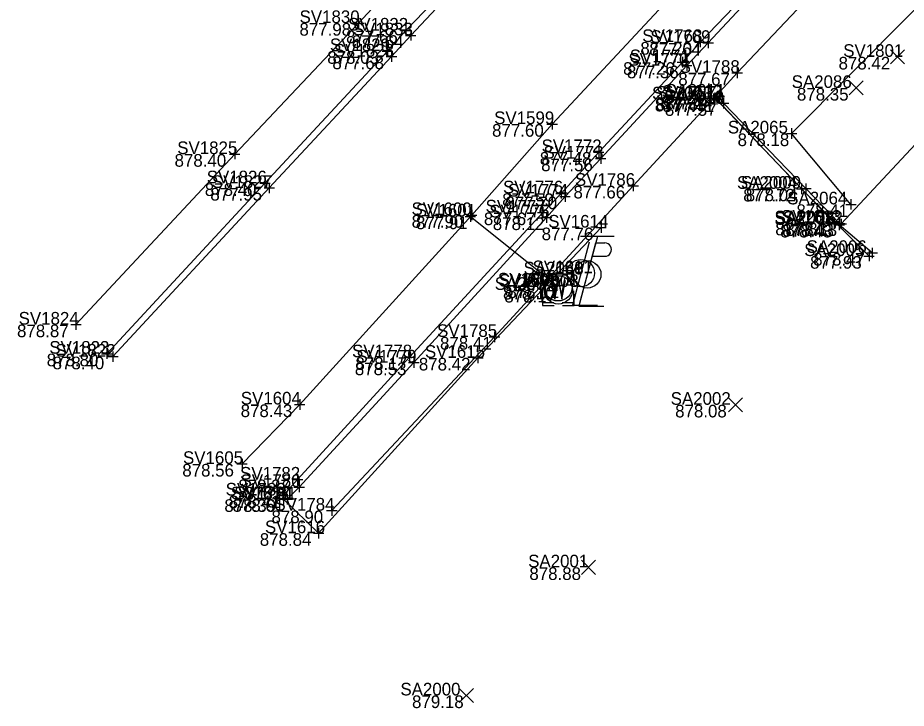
# Model space of a CAD drawing. Extents: x 1480001 to 1480402, y 379235 to 379603.
# Drawn here: x 1480030 to 1480114.4, y 379252.7 to 379318.4 of the extents above; entities that cross this region are included whole.
import ezdxf

# ---------------------------------------------------------------- set-up
doc = ezdxf.new("R2010")
doc.units = 0
for name, color, linetype in [('LT_X_Poles', 7, 'Continuous'), ('PV_X_Curb', 7, 'Continuous'), ('PV_X_Driveway', 7, 'Continuous'), ('PV_X_Parking_Lot', 7, 'Continuous'), ('PV_X_Walk', 7, 'Continuous'), ('SV_X_Break_Lines', 7, 'Continuous'), ('SV_X_Random_Point', 7, 'Continuous'), ('SV_X_Shot_Marker', 7, 'Continuous'), ('SV_X_Text_Elevation', 7, 'Continuous'), ('SV_X_Text_Name', 7, 'Continuous'), ('UT_X_Misc_Cells', 7, 'Continuous'), ('UT_X_Water', 7, 'Continuous'), ('UT_X_Water_Cells', 7, 'Continuous')]:
    doc.layers.add(name, color=color, linetype=linetype)

msp = doc.modelspace()

# ---------------------------------------------------------------- linework, layer by layer
at = {"layer": 'LT_X_Poles'}
for points in [[(1480084.258, 379297.063), (1480082.683, 379291.078), (1480085.046, 379291.078)], [(1480084.866, 379296.951), (1480083.291, 379290.966), (1480085.655, 379290.966)]]:
    msp.add_lwpolyline(points, dxfattribs=at)
for centre in [(1480083.471, 379294.11), (1480084.079, 379293.997)]:
    msp.add_circle(centre, 1.3, dxfattribs=at)
at = {"layer": 'PV_X_Curb'}
for points in [[(1480155.238, 379379.795), (1480153.548, 379379.014), (1480146.824, 379371.927), (1480145.567, 379370.605), (1480143.964, 379368.78), (1480128.12, 379351.892), (1480112.56, 379335.214), (1480098.785, 379320.255), (1480094.793, 379316.092), (1480093.124, 379314.172), (1480085.166, 379305.624), (1480081.585, 379301.702), (1480079.854, 379299.882), (1480067.172, 379286.11), (1480056.531, 379274.485), (1480055.169, 379272.969)], [(1480155.431, 379379.884), (1480153.98, 379378.667), (1480147.216, 379371.505), (1480146.047, 379370.27), (1480144.119, 379368.047), (1480128.647, 379351.629), (1480112.741, 379334.357), (1480099.146, 379319.858), (1480095.569, 379316.008), (1480093.53, 379313.846), (1480085.356, 379305.01), (1480081.967, 379301.397), (1480080.218, 379299.413), (1480067.589, 379285.613), (1480056.688, 379273.774), (1480055.547, 379272.623)], [(1480038.409, 379286.458), (1480053.445, 379302.656), (1480065.083, 379315.224), (1480066.832, 379317.181), (1480073.782, 379324.407), (1480080.94, 379332.144), (1480082.529, 379333.877), (1480097.272, 379349.731), (1480114.906, 379368.678)], [(1480038.979, 379286.174), (1480053.858, 379302.215), (1480065.464, 379314.71), (1480067.296, 379316.727), (1480074.111, 379324.008), (1480081.345, 379331.835), (1480082.794, 379333.357), (1480097.622, 379349.287), (1480115.163, 379368.135)], [(1480111.162, 379296.037), (1480108.032, 379298.711), (1480108.041, 379298.85), (1480104.856, 379302.149), (1480097.04, 379310.274), (1480096.612, 379310.903)]]:
    msp.add_lwpolyline(points, dxfattribs=at)
at = {"layer": 'PV_X_Driveway'}
msp.add_line((1480096.199, 379310.793), (1480107.531, 379298.913), dxfattribs=at)
msp.add_lwpolyline([(1480085.383, 379298.448), (1480073.674, 379286.062), (1480058.546, 379269.388), (1480055.218, 379272.613)], dxfattribs=at)
at = {"layer": 'PV_X_Parking_Lot'}
msp.add_lwpolyline([(1480096.393, 379310.64), (1480104.454, 379302.13), (1480110.858, 379295.74)], dxfattribs=at)
at = {"layer": 'PV_X_Walk'}
for points in [[(1480035.484, 379289.224), (1480050.568, 379305.437), (1480062.335, 379317.896), (1480064.038, 379319.719), (1480070.805, 379327.066), (1480078.054, 379334.946), (1480079.953, 379336.866), (1480094.208, 379352.393), (1480112.048, 379371.575), (1480117.348, 379377.211), (1480119.911, 379379.906), (1480121.511, 379381.77), (1480134.604, 379395.58), (1480136.695, 379398.148), (1480138.778, 379401.149), (1480140.004, 379404.725), (1480140.577, 379408.06), (1480140.982, 379411.311), (1480140.871, 379414.584), (1480140.225, 379417.636), (1480139.184, 379419.586), (1480133.124, 379425.845), (1480132.903, 379425.968), (1480114.834, 379442.96)], [(1480059.793, 379271.54), (1480075.261, 379288.048), (1480088.444, 379302.419), (1480096.088, 379310.695), (1480098.33, 379313.163), (1480111.975, 379327.613), (1480128.977, 379345.933), (1480145.46, 379363.52), (1480153.413, 379372.021), (1480155.772, 379374.786), (1480158.213, 379377.107), (1480160.137, 379378.801), (1480161.631, 379379.994)], [(1480108.223, 379298.793), (1480126.311, 379318.205), (1480145.385, 379338.742), (1480160.312, 379354.639), (1480170.225, 379345.82), (1480179.011, 379355.326), (1480188.24, 379365.647)]]:
    msp.add_lwpolyline(points, dxfattribs=at)
at = {"layer": 'SV_X_Break_Lines'}
msp.add_lwpolyline([(1480109.136, 379300.654), (1480103.503, 379307.396), (1480120.541, 379324.578), (1480124.787, 379337.805), (1480137.007, 379352.173), (1480144.932, 379357.565), (1480149.611, 379361.971), (1480150.052, 379364.189), (1480148.777, 379365.458), (1480163.875, 379379.601), (1480168.818, 379380.654), (1480172.802, 379381.332), (1480178.472, 379378.317), (1480184.655, 379372.421), (1480187.645, 379366.317)], dxfattribs=at)
at = {"layer": 'SV_X_Random_Point'}
for p, q in [((1480112.896, 379314.014), (1480114.23, 379315.349)), ((1480112.896, 379315.349), (1480114.23, 379314.014)), ((1480108.959, 379311.057), (1480110.292, 379312.392)), ((1480108.959, 379312.392), (1480110.292, 379311.057)), ((1480097.488, 379280.931), (1480098.821, 379282.266)), ((1480097.488, 379282.266), (1480098.821, 379280.931)), ((1480083.521, 379265.473), (1480084.854, 379266.808)), ((1480083.521, 379266.808), (1480084.854, 379265.473)), ((1480071.916, 379253.293), (1480073.249, 379254.628)), ((1480071.916, 379254.628), (1480073.249, 379253.293))]:
    msp.add_line(p, q, dxfattribs=at)
at = {"layer": 'SV_X_Shot_Marker'}
for p, q in [((1480061.835, 379317.896), (1480062.835, 379317.896)), ((1480062.335, 379318.396), (1480062.335, 379317.396)), ((1480062.335, 379317.896), (1480062.335, 379317.896)), ((1480066.832, 379317.681), (1480066.832, 379316.681)), ((1480066.332, 379317.181), (1480067.332, 379317.181)), ((1480066.832, 379317.181), (1480066.832, 379317.181)), ((1480067.296, 379317.227), (1480067.296, 379316.227)), ((1480066.796, 379316.727), (1480067.796, 379316.727)), ((1480067.296, 379316.727), (1480067.296, 379316.727)), ((1480094.293, 379316.092), (1480095.293, 379316.092)), ((1480094.793, 379316.592), (1480094.793, 379315.592)), ((1480094.793, 379316.092), (1480094.793, 379316.092)), ((1480095.069, 379316.008), (1480096.069, 379316.008)), ((1480095.569, 379316.508), (1480095.569, 379315.508)), ((1480095.569, 379316.008), (1480095.569, 379316.008)), ((1480064.583, 379315.224), (1480065.583, 379315.224)), ((1480065.083, 379315.724), (1480065.083, 379314.724)), ((1480065.083, 379315.224), (1480065.083, 379315.224)), ((1480065.464, 379315.21), (1480065.464, 379314.21)), ((1480064.964, 379314.71), (1480065.964, 379314.71)), ((1480065.464, 379314.71), (1480065.464, 379314.71)), ((1480093.124, 379314.672), (1480093.124, 379313.672)), ((1480093.53, 379314.346), (1480093.53, 379313.346)), ((1480092.624, 379314.172), (1480093.624, 379314.172)), ((1480093.03, 379313.846), (1480094.03, 379313.846)), ((1480093.124, 379314.172), (1480093.124, 379314.172)), ((1480093.53, 379313.846), (1480093.53, 379313.846)), ((1480098.33, 379313.663), (1480098.33, 379312.663)), ((1480097.83, 379313.163), (1480098.83, 379313.163)), ((1480098.33, 379313.163), (1480098.33, 379313.163)), ((1480096.088, 379311.195), (1480096.088, 379310.195)), ((1480096.112, 379310.903), (1480097.112, 379310.903)), ((1480096.199, 379311.293), (1480096.199, 379310.293)), ((1480096.393, 379311.14), (1480096.393, 379310.14)), ((1480096.612, 379311.403), (1480096.612, 379310.403)), ((1480096.612, 379310.903), (1480096.612, 379310.903)), ((1480095.588, 379310.695), (1480096.588, 379310.695)), ((1480095.699, 379310.793), (1480096.699, 379310.793)), ((1480095.893, 379310.64), (1480096.893, 379310.64)), ((1480096.088, 379310.695), (1480096.088, 379310.695)), ((1480096.199, 379310.793), (1480096.199, 379310.793)), ((1480096.393, 379310.64), (1480096.393, 379310.64)), ((1480096.54, 379310.274), (1480097.54, 379310.274)), ((1480097.04, 379310.774), (1480097.04, 379309.774)), ((1480097.04, 379310.274), (1480097.04, 379310.274)), ((1480080.736, 379308.789), (1480080.736, 379307.789)), ((1480080.236, 379308.289), (1480081.236, 379308.289)), ((1480080.736, 379308.289), (1480080.736, 379308.289)), ((1480103.503, 379307.896), (1480103.503, 379306.896)), ((1480103.003, 379307.396), (1480104.003, 379307.396)), ((1480103.503, 379307.396), (1480103.503, 379307.396)), ((1480050.568, 379305.937), (1480050.568, 379304.937)), ((1480085.166, 379306.124), (1480085.166, 379305.124)), ((1480050.068, 379305.437), (1480051.068, 379305.437)), ((1480050.568, 379305.437), (1480050.568, 379305.437)), ((1480084.666, 379305.624), (1480085.666, 379305.624)), ((1480084.856, 379305.01), (1480085.856, 379305.01)), ((1480085.166, 379305.624), (1480085.166, 379305.624)), ((1480085.356, 379305.51), (1480085.356, 379304.51)), ((1480085.356, 379305.01), (1480085.356, 379305.01)), ((1480052.945, 379302.656), (1480053.945, 379302.656)), ((1480053.445, 379303.156), (1480053.445, 379302.156)), ((1480053.445, 379302.656), (1480053.445, 379302.656)), ((1480053.858, 379302.715), (1480053.858, 379301.715)), ((1480088.444, 379302.919), (1480088.444, 379301.919)), ((1480104.454, 379302.63), (1480104.454, 379301.63)), ((1480104.856, 379302.649), (1480104.856, 379301.649)), ((1480053.358, 379302.215), (1480054.358, 379302.215)), ((1480053.858, 379302.215), (1480053.858, 379302.215)), ((1480081.085, 379301.702), (1480082.085, 379301.702)), ((1480081.585, 379302.202), (1480081.585, 379301.202)), ((1480081.585, 379301.702), (1480081.585, 379301.702)), ((1480081.967, 379301.897), (1480081.967, 379300.897)), ((1480087.944, 379302.419), (1480088.944, 379302.419)), ((1480088.444, 379302.419), (1480088.444, 379302.419)), ((1480103.954, 379302.13), (1480104.954, 379302.13)), ((1480104.356, 379302.149), (1480105.356, 379302.149)), ((1480104.454, 379302.13), (1480104.454, 379302.13)), ((1480104.856, 379302.149), (1480104.856, 379302.149)), ((1480081.467, 379301.397), (1480082.467, 379301.397)), ((1480081.967, 379301.397), (1480081.967, 379301.397)), ((1480109.136, 379301.154), (1480109.136, 379300.154)), ((1480072.97, 379299.999), (1480072.97, 379298.999)), ((1480073.091, 379300.137), (1480073.091, 379299.137)), ((1480079.854, 379300.382), (1480079.854, 379299.382)), ((1480080.218, 379299.913), (1480080.218, 379298.913)), ((1480108.636, 379300.654), (1480109.636, 379300.654)), ((1480109.136, 379300.654), (1480109.136, 379300.654)), ((1480072.47, 379299.499), (1480073.47, 379299.499)), ((1480072.591, 379299.637), (1480073.591, 379299.637)), ((1480072.97, 379299.499), (1480072.97, 379299.499)), ((1480073.091, 379299.637), (1480073.091, 379299.637)), ((1480079.354, 379299.882), (1480080.354, 379299.882)), ((1480079.718, 379299.413), (1480080.718, 379299.413)), ((1480079.854, 379299.882), (1480079.854, 379299.882)), ((1480080.218, 379299.413), (1480080.218, 379299.413)), ((1480107.531, 379299.413), (1480107.531, 379298.413)), ((1480108.032, 379299.211), (1480108.032, 379298.211)), ((1480108.041, 379299.35), (1480108.041, 379298.35)), ((1480108.223, 379299.293), (1480108.223, 379298.293)), ((1480084.883, 379298.448), (1480085.883, 379298.448)), ((1480085.383, 379298.948), (1480085.383, 379297.948)), ((1480085.383, 379298.448), (1480085.383, 379298.448)), ((1480107.031, 379298.913), (1480108.031, 379298.913)), ((1480107.531, 379298.913), (1480107.531, 379298.913)), ((1480107.532, 379298.711), (1480108.532, 379298.711)), ((1480107.541, 379298.85), (1480108.541, 379298.85)), ((1480107.723, 379298.793), (1480108.723, 379298.793)), ((1480108.032, 379298.711), (1480108.032, 379298.711)), ((1480108.041, 379298.85), (1480108.041, 379298.85)), ((1480108.223, 379298.793), (1480108.223, 379298.793)), ((1480111.162, 379296.537), (1480111.162, 379295.537)), ((1480110.358, 379295.74), (1480111.358, 379295.74)), ((1480110.662, 379296.037), (1480111.662, 379296.037)), ((1480110.858, 379296.24), (1480110.858, 379295.24)), ((1480110.858, 379295.74), (1480110.858, 379295.74)), ((1480111.162, 379296.037), (1480111.162, 379296.037)), ((1480081.181, 379293.441), (1480081.181, 379292.441)), ((1480080.681, 379292.941), (1480081.681, 379292.941)), ((1480081.181, 379292.941), (1480081.181, 379292.941)), ((1480034.984, 379289.224), (1480035.984, 379289.224)), ((1480035.484, 379289.724), (1480035.484, 379288.724)), ((1480035.484, 379289.224), (1480035.484, 379289.224)), ((1480075.261, 379288.548), (1480075.261, 379287.548)), ((1480074.761, 379288.048), (1480075.761, 379288.048)), ((1480075.261, 379288.048), (1480075.261, 379288.048)), ((1480037.909, 379286.458), (1480038.909, 379286.458)), ((1480038.409, 379286.958), (1480038.409, 379285.958)), ((1480038.409, 379286.458), (1480038.409, 379286.458)), ((1480038.979, 379286.674), (1480038.979, 379285.674)), ((1480067.172, 379286.61), (1480067.172, 379285.61)), ((1480073.674, 379286.562), (1480073.674, 379285.562)), ((1480038.479, 379286.174), (1480039.479, 379286.174)), ((1480038.979, 379286.174), (1480038.979, 379286.174)), ((1480066.672, 379286.11), (1480067.672, 379286.11)), ((1480067.089, 379285.613), (1480068.089, 379285.613)), ((1480067.172, 379286.11), (1480067.172, 379286.11)), ((1480067.589, 379286.113), (1480067.589, 379285.113)), ((1480067.589, 379285.613), (1480067.589, 379285.613)), ((1480073.174, 379286.062), (1480074.174, 379286.062)), ((1480073.674, 379286.062), (1480073.674, 379286.062)), ((1480056.248, 379281.628), (1480057.248, 379281.628)), ((1480056.748, 379282.128), (1480056.748, 379281.128)), ((1480056.748, 379281.628), (1480056.748, 379281.628)), ((1480051.266, 379276.474), (1480051.266, 379275.474)), ((1480050.766, 379275.974), (1480051.766, 379275.974)), ((1480051.266, 379275.974), (1480051.266, 379275.974)), ((1480056.531, 379274.985), (1480056.531, 379273.985)), ((1480056.031, 379274.485), (1480057.031, 379274.485)), ((1480056.188, 379273.774), (1480057.188, 379273.774)), ((1480056.531, 379274.485), (1480056.531, 379274.485)), ((1480056.688, 379274.274), (1480056.688, 379273.274)), ((1480056.688, 379273.774), (1480056.688, 379273.774)), ((1480054.669, 379272.969), (1480055.669, 379272.969)), ((1480055.169, 379273.469), (1480055.169, 379272.469)), ((1480055.169, 379272.969), (1480055.169, 379272.969)), ((1480055.218, 379273.113), (1480055.218, 379272.113)), ((1480055.547, 379273.123), (1480055.547, 379272.123)), ((1480054.718, 379272.613), (1480055.718, 379272.613)), ((1480055.047, 379272.623), (1480056.047, 379272.623)), ((1480055.218, 379272.613), (1480055.218, 379272.613)), ((1480055.547, 379272.623), (1480055.547, 379272.623)), ((1480059.293, 379271.54), (1480060.293, 379271.54)), ((1480059.793, 379272.04), (1480059.793, 379271.04)), ((1480059.793, 379271.54), (1480059.793, 379271.54)), ((1480058.546, 379269.888), (1480058.546, 379268.888)), ((1480058.046, 379269.388), (1480059.046, 379269.388)), ((1480058.546, 379269.388), (1480058.546, 379269.388))]:
    msp.add_line(p, q, dxfattribs=at)
at = {"layer": 'UT_X_Misc_Cells'}
for p, q in [((1480085.043, 379297.598), (1480083.436, 379291.598)), ((1480086.643, 379297.598), (1480083.443, 379297.598)), ((1480084.883, 379296.998), (1480085.733, 379296.998)), ((1480084.541, 379295.723), (1480085.733, 379295.723))]:
    msp.add_line(p, q, dxfattribs=at)
msp.add_circle((1480084.08, 379293.998), 1.3, dxfattribs=at)
msp.add_arc((1480085.745, 379296.36), 0.638, 268.8767, 91.1233, dxfattribs=at)
at = {"layer": 'UT_X_Water'}
msp.add_line((1480072.97, 379299.499), (1480081.181, 379292.941), dxfattribs=at)
msp.add_lwpolyline([(1480169.204, 379397.823), (1480165.761, 379394.087), (1480162.59, 379391.88), (1480159.156, 379388.706), (1480148.911, 379378.819), (1480120.344, 379350.087), (1480106.297, 379335.736), (1480080.736, 379308.289), (1480073.091, 379299.637), (1480056.748, 379281.628), (1480051.266, 379275.974)], dxfattribs=at)
at = {"layer": 'UT_X_Water_Cells'}
for p, q in [((1480081.303, 379292.82), (1480081.303, 379292.82)), ((1480081.33, 379292.525), (1480081.33, 379292.525))]:
    msp.add_line(p, q, dxfattribs=at)
for points in [[(1480080.903, 379294.32), (1480079.803, 379294.32), (1480079.803, 379293.22)], [(1480080.93, 379294.025), (1480079.83, 379294.025), (1480079.83, 379292.925)], [(1480082.803, 379293.22), (1480082.803, 379294.32), (1480081.703, 379294.32)], [(1480082.83, 379292.925), (1480082.83, 379294.025), (1480081.73, 379294.025)], [(1480080.636, 379293.72), (1480080.97, 379291.92), (1480081.303, 379293.72), (1480081.636, 379291.92), (1480081.97, 379293.72)], [(1480080.663, 379293.425), (1480080.996, 379291.625), (1480081.33, 379293.425), (1480081.663, 379291.625), (1480081.996, 379293.425)], [(1480079.803, 379292.42), (1480079.803, 379291.32), (1480080.903, 379291.32)], [(1480081.703, 379291.32), (1480082.803, 379291.32), (1480082.803, 379292.42)], [(1480079.83, 379292.125), (1480079.83, 379291.025), (1480080.93, 379291.025)], [(1480081.73, 379291.025), (1480082.83, 379291.025), (1480082.83, 379292.125)]]:
    msp.add_lwpolyline(points, dxfattribs=at)
for centre in [(1480081.303, 379292.82), (1480081.33, 379292.525)]:
    msp.add_circle(centre, 1.35, dxfattribs=at)

# ---------------------------------------------------------------- texts
at = {"layer": 'SV_X_Text_Elevation'}
for s, p in [('877.98', (1480056.723, 379316.696)), ('877.66', (1480061.154, 379315.981)), ('877.64', (1480061.703, 379315.527)), ('877.20', (1480089.124, 379314.892)), ('877.64', (1480089.976, 379314.808)), ('878.03', (1480059.367, 379314.024)), ('877.68', (1480059.852, 379313.51)), ('878.42', (1480107.96, 379313.482)), ('877.26', (1480087.483, 379312.972)), ('877.36', (1480087.852, 379312.646)), ('877.67', (1480092.727, 379311.963)), ('878.35', (1480104.004, 379310.524)), ('877.44', (1480091.028, 379309.703)), ('877.45', (1480090.495, 379309.495)), ('877.39', (1480090.587, 379309.593)), ('877.41', (1480091.234, 379309.44)), ('877.57', (1480091.456, 379309.074)), ('877.60', (1480075.029, 379307.089)), ('878.18', (1480098.364, 379306.196)), ('878.40', (1480044.852, 379304.237)), ('877.48', (1480079.563, 379304.424)), ('877.56', (1480079.697, 379303.81)), ('878.40', (1480047.729, 379301.456)), ('877.95', (1480048.255, 379301.015)), ('877.59', (1480075.992, 379300.502)), ('877.66', (1480082.766, 379301.219)), ('877.72', (1480098.898, 379300.93)), ('878.04', (1480099.149, 379300.949)), ('877.70', (1480076.298, 379300.197)), ('878.41', (1480103.958, 379299.454)), ('877.90', (1480067.384, 379298.437)), ('877.91', (1480067.801, 379298.299)), ('877.67', (1480074.251, 379298.682)), ('878.12', (1480075.098, 379298.213)), ('877.76', (1480079.742, 379297.248)), ('877.83', (1480101.947, 379297.713)), ('878.43', (1480102.42, 379297.511)), ('878.43', (1480102.61, 379297.593)), ('878.13', (1480102.912, 379297.65)), ('877.93', (1480105.255, 379294.54)), ('878.47', (1480105.55, 379294.837)), ('877.72', (1480077.915, 379292.91)), ('878.08', (1480078.354, 379292.798)), ('878.08', (1480078.354, 379292.798)), ('878.10', (1480076.069, 379291.62)), ('878.17', (1480076.2, 379291.325)), ('878.11', (1480076.485, 379291.741)), ('878.87', (1480029.881, 379288.024)), ('878.41', (1480070.083, 379286.848)), ('878.80', (1480032.702, 379285.258)), ('878.40', (1480033.263, 379284.974)), ('878.53', (1480061.986, 379284.413)), ('878.17', (1480062.042, 379284.91)), ('878.42', (1480068.071, 379284.862)), ('878.43', (1480051.136, 379280.428)), ('878.08', (1480092.429, 379280.398)), ('878.56', (1480045.588, 379274.774)), ('878.37', (1480050.909, 379273.285)), ('878.81', (1480051.519, 379272.574)), ('878.41', (1480049.991, 379271.769)), ('878.39', (1480049.587, 379271.413)), ('878.61', (1480050.359, 379271.423)), ('878.90', (1480054.067, 379270.34)), ('878.84', (1480052.953, 379268.188)), ('878.88', (1480078.575, 379264.94)), ('879.18', (1480067.424, 379252.761))]:
    msp.add_text(s, height=1.2, dxfattribs=at).set_placement(p)
at = {"layer": 'SV_X_Text_Name'}
for s, p in [('SV1830', (1480056.733, 379317.896)), ('SV1832', (1480061.343, 379317.181)), ('SV1833', (1480061.798, 379316.727)), ('SV1768', (1480089.304, 379316.092)), ('SV1769', (1480090.08, 379316.008)), ('SV1829', (1480059.613, 379315.224)), ('SV1828', (1480059.994, 379314.71)), ('SV1771', (1480088.116, 379314.172)), ('SV1801', (1480108.404, 379314.682)), ('SV1770', (1480087.985, 379313.846)), ('SV1788', (1480092.86, 379313.163)), ('SA2086', (1480103.503, 379311.724)), ('SA2003', (1480090.233, 379310.64)), ('SV1787', (1480090.628, 379310.695)), ('SV1612', (1480091.183, 379310.793)), ('SA2011', (1480091.472, 379310.903)), ('SA2010', (1480091.362, 379310.274)), ('SV1599', (1480075.228, 379308.289)), ('SA2065', (1480097.437, 379307.396)), ('SV1772', (1480079.734, 379305.624)), ('SV1825', (1480045.108, 379305.437)), ('SV1773', (1480079.915, 379305.01)), ('SV1826', (1480047.909, 379302.656)), ('SV1827', (1480048.398, 379302.215)), ('SV1786', (1480082.908, 379302.419)), ('SA2004', (1480098.303, 379302.13)), ('SA2009', (1480098.686, 379302.149)), ('SV1776', (1480076.068, 379301.702)), ('SV1774', (1480076.535, 379301.397)), ('SA2064', (1480103.08, 379300.654)), ('SV1600', (1480067.375, 379299.637)), ('SV1777', (1480074.413, 379299.882)), ('SV1601', (1480067.792, 379299.499)), ('SV1775', (1480074.777, 379299.413)), ('SA2008', (1480101.872, 379298.85)), ('SA2007', (1480101.872, 379298.711)), ('SV1613', (1480102.506, 379298.913)), ('SA2012', (1480102.658, 379298.793)), ('SV1614', (1480080.367, 379298.448)), ('SA2005', (1480104.698, 379295.74)), ('SA2006', (1480104.927, 379296.037)), ('SA2089', (1480078.023, 379293.998)), ('SA2088', (1480078.023, 379293.998)), ('SV1611', (1480078.88, 379294.11)), ('SV1602', (1480075.579, 379292.941)), ('SV1603', (1480075.691, 379292.82)), ('SA2087', (1480075.283, 379292.525)), ('SV1824', (1480030.033, 379289.224)), ('SV1785', (1480069.801, 379288.048)), ('SV1823', (1480032.949, 379286.458)), ('SV1822', (1480033.528, 379286.174)), ('SV1778', (1480061.721, 379286.11)), ('SV1615', (1480068.649, 379286.062)), ('SV1779', (1480062.138, 379285.613)), ('SV1604', (1480051.146, 379281.628)), ('SA2002', (1480092.004, 379281.598)), ('SV1605', (1480045.654, 379275.974)), ('SV1782', (1480051.08, 379274.485)), ('SV1780', (1480051.124, 379273.774)), ('SV1783', (1480049.709, 379272.969)), ('SV1617', (1480050.193, 379272.613)), ('SV1781', (1480050.52, 379272.623)), ('SV1784', (1480054.342, 379271.54)), ('SV1616', (1480053.445, 379269.388)), ('SA2001', (1480078.461, 379266.14)), ('SA2000', (1480066.318, 379253.961))]:
    msp.add_text(s, height=1.2, dxfattribs=at).set_placement(p)

doc.saveas('drawing.dxf')
